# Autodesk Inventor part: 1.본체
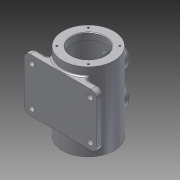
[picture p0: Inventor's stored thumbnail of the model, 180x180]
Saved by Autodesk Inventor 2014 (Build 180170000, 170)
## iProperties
Created: 2014-12
Part Number: 1.본체
Material: 알루미늄 6061
Document SubType Name: Modeling
Designer: Owner
Density: 2.71 g/cm^3
Appearance: 알루미늄 - 평지
Mass: 1294.01 g
Surface Area: 1040.12 cm^2
Volume: 477.493 cm^3
Author: Owner
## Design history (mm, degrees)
sketch "스케치1"
  geometry: C1 r 46 at (0, 0); 1 further point
  constraints: 1 centre point, 1 coincident
  dimensions: "d0" = 92 diameter of C1
extrude "돌출1" new body sketch "스케치1" stored distance "d1" = 140; taper "d2" = 0 deg
node "작업 평면1"
sketch "스케치2"
  geometry: L1 (-65, -40)-(65, -40); L2 (65, -40)-(65, 55); L3 (65, 55)-(-65, 55); L4 (-65, 55)-(-65, -40); L5 (46, 70)-(-46, 70) reference; 1 further point
  constraints: 8 end point, 2 parallel, 1 horizontal, 1 perpendicular
  dimensions: "d4" = 130 distance between parallel lines of L2 L4; "d5" = 65 distance from line of L4 point (0, 0); "d6" = 95 distance between parallel lines of L3 L1; "d7" = 15 distance between parallel lines of L5 L3
extrude "돌출2" join sketch "스케치2" distance "d8" = 12; taper "d9" = 0 deg
node "작업 평면2"
sketch "스케치3"
  geometry: L1 (-46, -70)-(46, -70) reference; L2 (46, 70)-(-46, 70) reference; C1 r 20 at (0, -30); C2 r 20 at (0, 30); 1 further point
  constraints: 2 centre point, 1 vertical alignment
  dimensions: "d11" = 40 diameter of C1; "d12" = 40 diameter of C2; "d13" = 40 distance from line of L1 C1.centre; "d14" = 60 distance of C2.centre C1.centre; "d15" = 40 distance from line of L2 C2.centre
extrude "돌출3" join sketch "스케치3" stored distance "d16" = 12; taper "d17" = 0 deg
node "작업 평면3"
sketch "스케치4"
  geometry: L1 (65, 55)-(-65, 55) reference; L2 (-65, -40)-(65, -40) reference; L3 (65, -40)-(65, 55) reference; L4 (-65, 55)-(-65, -40) reference; C1 r 5.5 at (-52.5, -27.5); C2 r 5.5 at (-52.5, 42.5); C3 r 5.5 at (52.5, 42.5); C4 r 5.5 at (52.5, -27.5); 1 further point
  constraints: 4 centre point, 3 equal radius, 2 horizontal alignment, 2 vertical alignment
  dimensions: "d19" = 11 diameter of C1; "d20" = 12.5 distance from line of L1 C3.centre; "d21" = 12.5 distance from line of L2 C1.centre; "d22" = 12.5 distance from line of L3 C4.centre; "d23" = 12.5 distance from line of L4 C1.centre
extrude "돌출4" cut sketch "스케치4" distance "d24" = 12; taper "d25" = 0 deg
sketch "스케치5"
  geometry: L1 (46, 70)-(-46, 70) reference; L2 (-46, -70)-(46, -70) reference; L3 (0, 70)-(0, -70); L4 (30, 70)-(30, 58); L5 (30, 58)-(37.5, 58); L6 (37.5, 58)-(37.5, -58); L7 (37.5, -58)-(30, -58); L8 (30, -58)-(30, -70); L9 (30, 70)-(0, 70); L10 (30, -70)-(0, -70); 1 further point
  constraints: 16 end point, 3 collinear, 3 parallel, 2 midpoint, 2 point on line, 1 perpendicular
  dimensions: "d26" = 12 distance between parallel lines of L9 L5; "d27" = 12 distance between parallel lines of L2 L7; "d28" = 60 diameter of L4 L3; "d29" = 60 diameter of L8 L3; "d30" = 75 diameter of L6 L3
revolve "회전1" sketch "스케치5" stored, may be unused: angle "d31" = 90 deg
fillet "모깎기1" dims "d32" = 10
hole "구멍1" diameter "d35" = 25; stored, may be unused: countersink angle "d39" = 90 deg, drill point angle "d41" = 0 deg; dims "d36" = 6, "d37" = 30, "d38" = 8, "d40" = 25, "d42" = 10, "d43" = 10
hole "구멍2" diameter "d46" = 25; stored, may be unused: countersink angle "d50" = 90 deg, drill point angle "d52" = 0 deg; dims "d47" = 6, "d48" = 30, "d49" = 8, "d51" = 25, "d53" = 10, "d54" = 10
sketch "스케치6" dims "d6" = 95
  geometry: L1 (-65, 30)-(-65, -45) reference; C1 r 5.5 at (-52.5, 27.5) reference; 2 further points
  constraints: 1 other
  dimensions: "d55" = 35 vertical distance of C1.centre point (-57, -7.5); "d56" = 8 distance from line of L1 point (-57, -7.5)
feature "엠보싱1" sketch "스케치6" dims "d18" = -38, "d57" = 1, "d58" = 0
sketch "스케치7"
  geometry: L1 (0, 0)-(28.284, 28.284); L2 (0, 0)-(40, 0); L3 (0, 0)-(-28.284, 28.284); L4 (0, 0)-(-28.284, -28.284); L5 (0, 0)-(28.284, -28.284); C1 r 30 at (0, 0) reference; C2 r 46 at (0, 0) reference; 4 further points
  constraints: 10 end point, 4 coincident, 1 equal length, 1 horizontal, 13 other
  dimensions: "d59" = 40 distance of L1.start L1.end; "d60" = 45 deg angle of L2 L1; "d63" = 360 deg dimension on C1.centre L1.end (derived)
hole "구멍3" sketch "스케치7" at (-28.284, 28.284), (28.284, 28.284), (-28.284, -28.284), (28.284, -28.284) diameter "d65" = 3.242; stored, may be unused: countersink angle "d69" = 90 deg, drill point angle "d71" = 118 deg; dims "d66" = 8, "d67" = 30, "d68" = 8, "d70" = 10
sketch "스케치8"
  geometry: L1 (0, 0)-(28.284, 28.284); L2 (0, 0)-(40, 0); L3 (0, 0)-(-28.284, 28.284); L4 (0, 0)-(-28.284, -28.284); L5 (0, 0)-(28.284, -28.284); C1 r 30 at (0, 0) reference; C2 r 46 at (0, 0) reference; 4 further points
  constraints: 10 end point, 4 coincident, 1 equal length, 1 horizontal, 13 other
  dimensions: "d72" = 40 distance of L1.start L1.end; "d73" = 45 deg angle of L2 L1; "d76" = 360 deg dimension on C1.centre L1.end (derived)
hole "구멍4" sketch "스케치8" at (-28.284, 28.284), (28.284, 28.284), (-28.284, -28.284), (28.284, -28.284) diameter "d78" = 3.242; stored, may be unused: countersink angle "d82" = 90 deg, drill point angle "d84" = 118 deg; dims "d79" = 8, "d80" = 30, "d81" = 8, "d83" = 10
fillet "모깎기2" dims "d85" = 3
chamfer "모따기1" distance "d86" = 1; stored, may be unused: second distance "d87" = 2, angle "d88" = 45 deg
fillet "모깎기3" dims "d89" = 5
fillet "모깎기4" dims "d90" = 3
fillet "모깎기5" dims "d91" = 3
fillet "모깎기6" dims "d92" = 3
node "솔리드1"
other parameters: "d10" = 56
